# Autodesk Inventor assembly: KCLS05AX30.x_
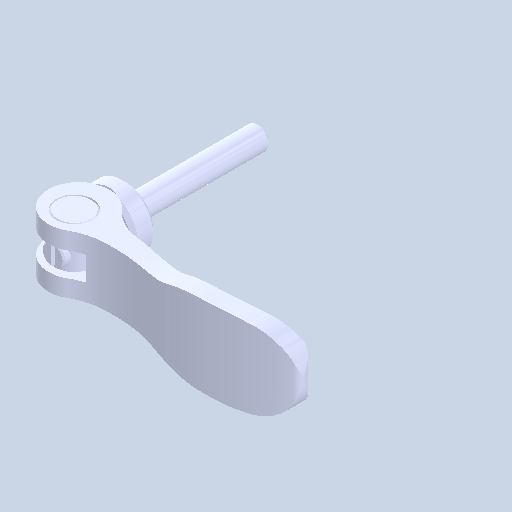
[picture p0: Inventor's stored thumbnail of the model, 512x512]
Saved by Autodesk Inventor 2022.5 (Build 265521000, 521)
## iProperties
Created: 2024-08
Part Number: KCLS05AX30.x_
Document SubType Name: Assembly
Designer: ImaoCorp
Author: ImaoCorp
Sending System: SOLIDWORKS 2022-2022290
MC: AMD64
MC_MODEL: Intel64 Family 6 Model 60 Stepping 3, GenuineIntel
OS: Windows_NT
FRU: Parasolid Version 33.1, build 260,  4-25-2022
FORMAT: text
GUISE: transmit
KEY: FILEKCLS05AX30.x_t
DATE: Thu Aug 29 10:54:30 2024
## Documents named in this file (5)
- Y:\5.更新分\2024年対応\1001_KCL\データ\kcls05ax30\KCLS05AX30.x_.iam
- Y:\5.更新分\2024年対応\1001_KCL\データ\kcls05ax30\KCLS05AX30_01.ipt
- Y:\5.更新分\2024年対応\1001_KCL\データ\kcls05ax30\KCLS05AX30_02.ipt
- Y:\5.更新分\2024年対応\1001_KCL\データ\kcls05ax30\KCLS05AX30_03.ipt
- Y:\5.更新分\2024年対応\1001_KCL\データ\kcls05ax30\KCLS05AX30_04.ipt
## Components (4 placed, 4 different names)
1. KCLS05AX30_01
2. KCLS05AX30_02
3. KCLS05AX30_03
4. KCLS05AX30_04
